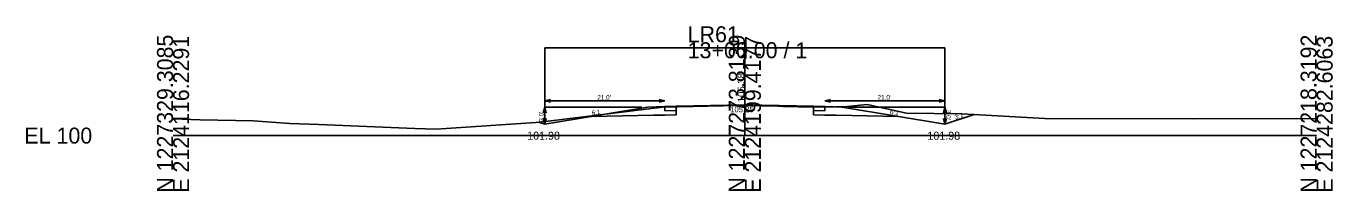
# Model space of a CAD drawing. Extents: x 2126751 to 2128979, y 1225108 to 1234639.
# Drawn here: x 2127750.9 to 2127979.4, y 1228107.5 to 1228136.4 of the extents above; entities that cross this region are included whole.
import ezdxf

# ---------------------------------------------------------------- set-up
doc = ezdxf.new("R2010")
doc.units = 0
for name, color, linetype in [('XS_CELL', 7, 'Continuous'), ('XS_M_DITCH', 7, 'Continuous'), ('XS_P_FINISHED_GRADE', 7, 'Continuous'), ('XS_P_FINISHED_GRADE_ELEV_TX', 7, 'Continuous'), ('XS_P_SUBGRADE_GRANULAR', 7, 'Continuous'), ('XS_P_SUBGRADE_LEVELING', 7, 'Continuous'), ('XS_P_SUBGRADE_PAVEMENT', 7, 'Continuous'), ('XS_P_TX_CLEARZONE', 7, 'Continuous'), ('XS_P_TX_DCH', 7, 'Continuous'), ('XS_P_TX_FS_BS', 7, 'Continuous'), ('XS_X_GROUND', 7, 'Continuous'), ('XS_X_GROUND_TX', 7, 'Continuous')]:
    doc.layers.add(name, color=color, linetype=linetype)

msp = doc.modelspace()

# ---------------------------------------------------------------- linework, layer by layer
at = {"layer": 'XS_CELL'}
for p, q in [((2127876.61, 1228117.21), (2127876.61, 1228133.57)), ((2127776.61, 1228117.21), (2127876.61, 1228117.21)), ((2127876.61, 1228117.21), (2127976.61, 1228117.21))]:
    msp.add_line(p, q, dxfattribs=at)
at = {"layer": 'XS_M_DITCH'}
for p, q in [((2127841.61, 1228119.19), (2127841.61, 1228132.59)), ((2127841.61, 1228132.59), (2127911.61, 1228132.59)), ((2127911.61, 1228132.59), (2127911.61, 1228119.19))]:
    msp.add_line(p, q, dxfattribs=at)
at = {"layer": 'XS_P_FINISHED_GRADE'}
for p, q in [((2127859.61, 1228122.19), (2127841.61, 1228119.19)), ((2127862.61, 1228122.31), (2127859.61, 1228122.19)), ((2127864.61, 1228122.35), (2127862.61, 1228122.31)), ((2127864.61, 1228122.35), (2127876.61, 1228122.59)), ((2127876.61, 1228122.59), (2127888.61, 1228122.35)), ((2127888.61, 1228122.35), (2127890.61, 1228122.31)), ((2127890.61, 1228122.31), (2127893.61, 1228122.19)), ((2127893.61, 1228122.19), (2127911.61, 1228119.19)), ((2127911.61, 1228119.19), (2127916.72, 1228120.89)), ((2127841.61, 1228119.19), (2127840.54, 1228119.54))]:
    msp.add_line(p, q, dxfattribs=at)
at = {"layer": 'XS_P_SUBGRADE_GRANULAR'}
for p, q in [((2127860.61, 1228120.77), (2127849.79, 1228120.55)), ((2127862.61, 1228120.81), (2127860.61, 1228120.77)), ((2127864.61, 1228120.85), (2127862.61, 1228120.81)), ((2127864.61, 1228120.85), (2127864.61, 1228121.6)), ((2127888.61, 1228120.85), (2127888.61, 1228121.6)), ((2127888.61, 1228120.85), (2127890.61, 1228120.81)), ((2127890.61, 1228120.81), (2127892.61, 1228120.77)), ((2127892.61, 1228120.77), (2127903.43, 1228120.55))]:
    msp.add_line(p, q, dxfattribs=at)
at = {"layer": 'XS_P_SUBGRADE_LEVELING'}
for p, q in [((2127864.61, 1228122.26), (2127872.82, 1228122.41)), ((2127864.61, 1228122.35), (2127864.61, 1228122.26)), ((2127872.82, 1228122.41), (2127876.47, 1228122.46)), ((2127876.47, 1228122.46), (2127882.42, 1228122.35)), ((2127882.42, 1228122.35), (2127883.23, 1228122.33)), ((2127883.23, 1228122.33), (2127888.61, 1228122.22)), ((2127888.61, 1228122.35), (2127888.61, 1228122.22))]:
    msp.add_line(p, q, dxfattribs=at)
at = {"layer": 'XS_P_SUBGRADE_PAVEMENT'}
for p, q in [((2127862.61, 1228121.56), (2127862.61, 1228122.31)), ((2127864.61, 1228121.6), (2127862.61, 1228121.56)), ((2127864.61, 1228121.6), (2127864.61, 1228122.26)), ((2127888.61, 1228121.6), (2127888.61, 1228122.22)), ((2127888.61, 1228121.6), (2127890.61, 1228121.56)), ((2127890.61, 1228121.56), (2127890.61, 1228122.31))]:
    msp.add_line(p, q, dxfattribs=at)
at = {"layer": 'XS_P_TX_CLEARZONE'}
for p, q in [((2127841.61, 1228123.31), (2127842.61, 1228123.56)), ((2127841.61, 1228123.31), (2127842.61, 1228123.06)), ((2127862.61, 1228123.31), (2127841.61, 1228123.31)), ((2127862.61, 1228123.31), (2127861.61, 1228123.56)), ((2127862.61, 1228123.31), (2127861.61, 1228123.06)), ((2127890.61, 1228123.31), (2127891.61, 1228123.56)), ((2127890.61, 1228123.31), (2127891.61, 1228123.06)), ((2127890.61, 1228123.31), (2127911.61, 1228123.31)), ((2127911.61, 1228123.31), (2127910.61, 1228123.56)), ((2127911.61, 1228123.31), (2127910.61, 1228123.06)), ((2127841.61, 1228122.19), (2127841.36, 1228121.19)), ((2127841.61, 1228122.19), (2127841.86, 1228121.19)), ((2127841.61, 1228122.19), (2127841.61, 1228119.19)), ((2127858.61, 1228122.19), (2127841.61, 1228122.19)), ((2127894.61, 1228122.19), (2127911.61, 1228122.19)), ((2127911.61, 1228122.19), (2127911.36, 1228121.19)), ((2127911.61, 1228122.19), (2127911.61, 1228119.19)), ((2127911.61, 1228122.19), (2127911.86, 1228121.19)), ((2127841.61, 1228119.19), (2127841.36, 1228120.19)), ((2127841.61, 1228119.19), (2127841.86, 1228120.19)), ((2127911.61, 1228119.19), (2127911.36, 1228120.19)), ((2127911.61, 1228119.19), (2127911.86, 1228120.19))]:
    msp.add_line(p, q, dxfattribs=at)
at = {"layer": 'XS_X_GROUND'}
for p, q in [((2127842.22, 1228119.74), (2127862.2, 1228122.22)), ((2127862.2, 1228122.22), (2127872.82, 1228122.41)), ((2127872.82, 1228122.41), (2127876.47, 1228122.46)), ((2127876.47, 1228122.46), (2127882.42, 1228122.35)), ((2127882.42, 1228122.35), (2127883.23, 1228122.33)), ((2127883.23, 1228122.33), (2127890.37, 1228122.18)), ((2127890.37, 1228122.18), (2127894.48, 1228122.34)), ((2127894.48, 1228122.34), (2127897.98, 1228122.66)), ((2127897.98, 1228122.66), (2127904.87, 1228121.14)), ((2127904.87, 1228121.14), (2127914.56, 1228121)), ((2127914.56, 1228121), (2127929.06, 1228120.23)), ((2127776.61, 1228120.13), (2127781.36, 1228120)), ((2127781.36, 1228120), (2127790.61, 1228119.82)), ((2127790.61, 1228119.82), (2127797.04, 1228119.36)), ((2127797.04, 1228119.36), (2127802.11, 1228119.14)), ((2127802.11, 1228119.14), (2127818.89, 1228118.48)), ((2127818.89, 1228118.48), (2127822.64, 1228118.35)), ((2127822.64, 1228118.35), (2127840.03, 1228119.48)), ((2127840.03, 1228119.48), (2127842.22, 1228119.74)), ((2127929.06, 1228120.23), (2127954.95, 1228120.14)), ((2127954.95, 1228120.14), (2127976.61, 1228120.21))]:
    msp.add_line(p, q, dxfattribs=at)

# ---------------------------------------------------------------- texts
at = {"layer": 'XS_CELL'}
for s, p in [('N 1227329.3085', (2127776.61, 1228107.21)), ('E 2124116.2291', (2127779.41, 1228107.21)), ('N 1227273.8139', (2127876.61, 1228107.21)), ('E 2124199.4177', (2127879.41, 1228107.21)), ('N 1227218.3192', (2127976.61, 1228107.21)), ('E 2124282.6063', (2127979.41, 1228107.21))]:
    msp.add_text(s, height=2.8, rotation=90, dxfattribs=at).set_placement(p)
for s, p in [('LR61', (2127866.61, 1228133.57)), ('13+00.00 / 1', (2127866.61, 1228130.77)), ('EL 100', (2127750.61, 1228115.81))]:
    msp.add_text(s, height=2.8, dxfattribs=at).set_placement(p)
at = {"layer": 'XS_P_FINISHED_GRADE_ELEV_TX'}
msp.add_text(' 105.38', height=1.25, rotation=90, dxfattribs=at).set_placement((2127876.61, 1228122.59))
at = {"layer": 'XS_P_TX_CLEARZONE'}
for p in [(2127850.82, 1228123.51), (2127899.82, 1228123.51)]:
    msp.add_text("21.0'", height=0.8, dxfattribs=at).set_placement(p)
for rotation, p in [(90, (2127841.41, 1228119.66)), (270, (2127911.81, 1228121.71))]:
    msp.add_text("3.0'", height=0.8, rotation=rotation, dxfattribs=at).set_placement(p)
at = {"layer": 'XS_P_TX_DCH'}
for p in [(2127838.54, 1228116.49), (2127908.54, 1228116.49)]:
    msp.add_text('101.98', height=1.4, dxfattribs=at).set_placement(p)
at = {"layer": 'XS_P_TX_FS_BS'}
for s, rotation, p in [('6:1', 9.4623, (2127849.89, 1228120.77)), ('6:1', 350.5377, (2127901.95, 1228121)), ('3:1', 18.4349, (2127913.45, 1228120.01))]:
    msp.add_text(s, height=0.8, rotation=rotation, dxfattribs=at).set_placement(p)
at = {"layer": 'XS_X_GROUND_TX'}
msp.add_text('105.25', height=1, dxfattribs=at).set_placement((2127874.05, 1228121.3))

doc.saveas('drawing.dxf')
